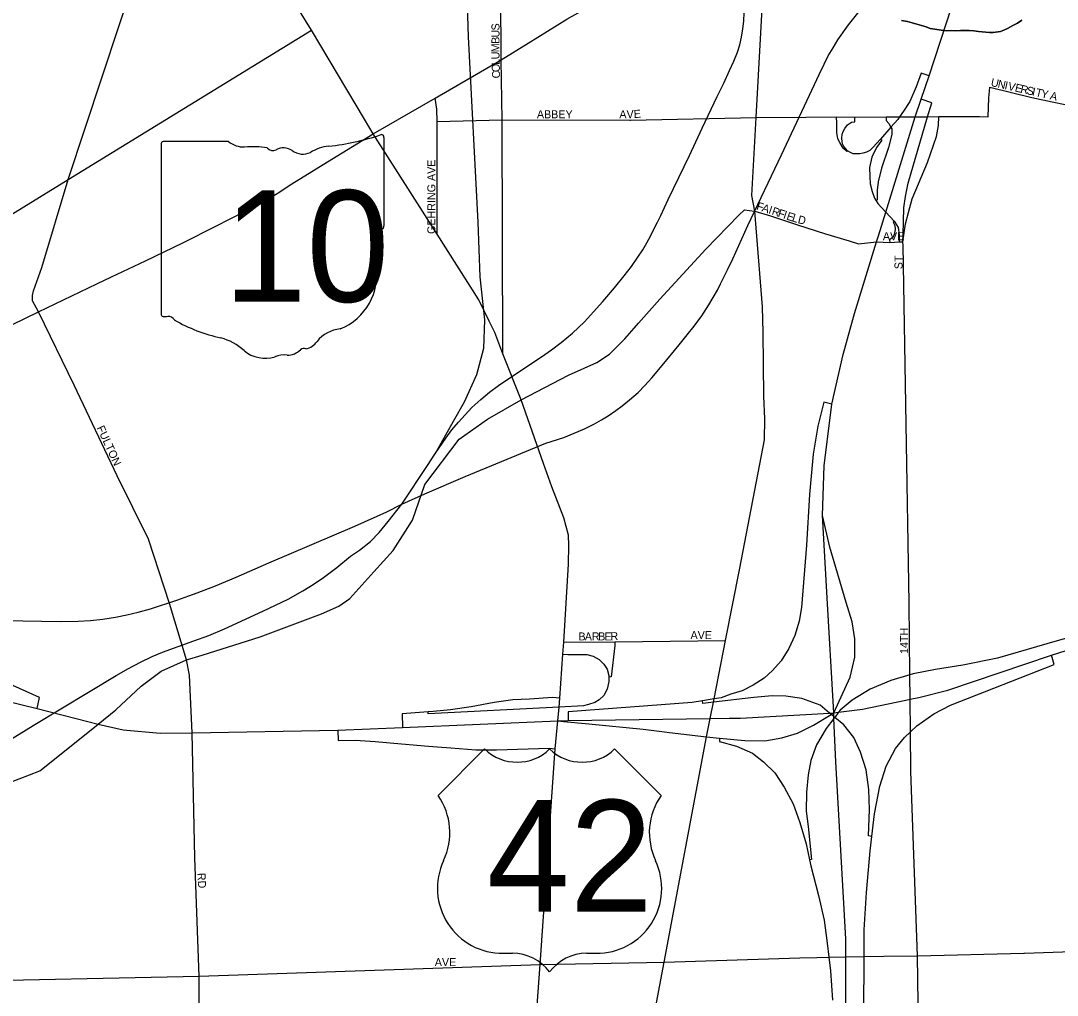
# Model space of a CAD drawing. Extents: x -561 to 1170, y 0 to 846.
# Drawn here: x 229.07 to 246.55, y 259.37 to 275.8 of the extents above; entities that cross this region are included whole.
import ezdxf

# ---------------------------------------------------------------- set-up
doc = ezdxf.new("R2010")
doc.units = 0
for name, color, linetype in [('GM_X_City_Street', 7, 'Continuous'), ('GM_X_City_Street_Text', 7, 'Continuous'), ('GM_X_Interchange_Ramps', 7, 'Continuous'), ('GM_X_Interstate_Route', 7, 'Continuous'), ('GM_X_Major_River', 7, 'Continuous'), ('GM_X_Rail_Line', 7, 'Continuous'), ('GM_X_State_Location', 7, 'Continuous'), ('GM_X_State_Route', 7, 'Continuous'), ('GM_X_State_Shield', 7, 'Continuous'), ('GM_X_US_Location', 7, 'Continuous'), ('GM_X_US_Route', 7, 'Continuous'), ('GM_X_US_Shield', 7, 'Continuous')]:
    doc.layers.add(name, color=color, linetype=linetype)

msp = doc.modelspace()

# ---------------------------------------------------------------- linework, layer by layer
at = {"layer": 'GM_X_City_Street'}
for points in [[(241.587, 270.54), (241.581, 270.976), (241.449, 272.588), (241.4, 272.851), (241.47, 274.167), (241.587, 276.31), (241.601, 276.652), (241.62, 276.918), (241.615, 277.331), (241.596, 277.763), (241.582, 278.503), (241.5, 280.566), (241.5, 280.686), (241.519, 280.834), (241.598, 281.16), (242.005, 282.324), (242.335, 283.286)], [(232.08, 259.688), (232.008, 261.687), (231.963, 263.79), (231.915, 264.765), (231.869, 265.021), (231.578, 265.97), (231.224, 267.059), (230.696, 268.124), (229.972, 269.654), (229.373, 270.892), (229.271, 271.075), (229.271, 271.165), (229.29, 271.245), (229.43, 271.639), (229.871, 273.119), (230.734, 275.717), (231.217, 277.172)], [(237.17, 275.418), (237.161, 276.52)], [(215.146, 270.207), (225.325, 270.329), (226.891, 271.29), (229.871, 273.119), (233.973, 275.638)], [(237.203, 270.179), (237.187, 274.125), (237.172, 275.138), (237.17, 275.418)], [(245.239, 274.18), (245.381, 274.179), (245.392, 274.495), (245.404, 274.608)], [(245.404, 274.608), (245.412, 274.674), (246.122, 274.503), (246.463, 274.43)], [(236.093, 272.196), (236.095, 274.098), (236.085, 274.307), (236.059, 274.49)], [(246.463, 274.43), (246.68, 274.383), (246.805, 274.341), (246.874, 274.31)], [(236.095, 274.098), (237.187, 274.125), (239.344, 274.123)], [(239.344, 274.123), (239.352, 274.123), (241.47, 274.167), (242.311, 274.171)], [(242.311, 274.171), (242.828, 274.175), (243.135, 274.172), (243.664, 274.174), (243.89, 274.174), (243.95, 274.175)], [(243.95, 274.175), (244.153, 274.175), (244.363, 274.178), (244.553, 274.18), (245.239, 274.18)], [(244.042, 272.564), (244.104, 272.793), (244.359, 273.404), (244.511, 273.846), (244.546, 274.032), (244.553, 274.18)], [(239.49, 270.7), (239.846, 271.104), (240.621, 271.945), (241.177, 272.521), (241.277, 272.607), (241.445, 272.588)], [(241.445, 272.588), (241.449, 272.588), (241.711, 272.508), (242.168, 272.356), (242.641, 272.207), (243.037, 272.087)], [(243.948, 272.006), (243.947, 272.072), (243.989, 272.373), (244.042, 272.564)], [(243.037, 272.087), (243.197, 272.038), (243.503, 272.067), (243.724, 272.06), (243.884, 272.068), (243.947, 272.072)], [(244.24, 256.524), (244.219, 257.049), (244.218, 258.034), (244.189, 260.034), (244.079, 263.14), (244.072, 263.81), (244.066, 264.357), (244.062, 264.771), (244.049, 265.982), (243.948, 272.006)], [(232.134, 265.104), (233.109, 265.408), (234.145, 265.798), (234.434, 265.928), (234.621, 266.059), (235.024, 266.504), (235.353, 266.866), (235.68, 267.38), (235.886, 267.979), (236.466, 268.745), (236.94, 269.081), (237.509, 269.405), (238.307, 269.819), (238.786, 270.035), (238.996, 270.176), (239.257, 270.435), (239.413, 270.613), (239.49, 270.7)], [(239.918, 259.925), (239.918, 259.925), (240.637, 263.724), (240.697, 264.032), (240.751, 264.307), (240.763, 264.364), (240.956, 265.347), (241.195, 266.57), (241.612, 268.73), (241.62, 269.087), (241.601, 269.468), (241.587, 270.54)], [(238.229, 265.319), (239.09, 265.328), (240.956, 265.347)], [(227.907, 262.547), (228.517, 262.813), (229.393, 263.151), (229.894, 263.549), (230.38, 263.941), (230.673, 264.178), (231.102, 264.578), (231.442, 264.83), (231.869, 265.021), (232.134, 265.104)], [(245.996, 260.076), (251.137, 260.26)], [(244.189, 260.034), (245.987, 260.076), (245.996, 260.076)], [(225.431, 259.49), (227.763, 259.6), (232.08, 259.688), (237.829, 259.885)], [(237.829, 259.885), (239.918, 259.925), (242.209, 260.001), (242.493, 260.005)], [(238.774, 253.841), (239.918, 259.925)], [(242.493, 260.005), (242.698, 260.009), (242.986, 260.014), (243.294, 260.019), (243.624, 260.025)], [(243.624, 260.025), (244.189, 260.034)], [(228.122, 248.14), (228.208, 248.321), (228.22, 248.347), (228.787, 249.591), (229.314, 250.773), (230.194, 252.768), (230.9, 254.246), (231.72, 255.969), (231.913, 256.389), (232.133, 256.831), (232.088, 258.264), (232.08, 259.688)]]:
    msp.add_lwpolyline(points, dxfattribs=at)
at = {"layer": 'GM_X_Interchange_Ramps'}
for points in [[(244.387, 274.865), (244.256, 274.911), (244.168, 274.681), (244.06, 274.436), (243.956, 274.274), (243.89, 274.174), (243.861, 274.132), (243.744, 274), (243.567, 273.8), (243.441, 273.658), (243.388, 273.611), (243.332, 273.579), (243.269, 273.563), (243.217, 273.555), (243.161, 273.552), (243.109, 273.555), (243.06, 273.574), (243.014, 273.606), (242.95, 273.677), (242.934, 273.709), (242.921, 273.756), (242.917, 273.819), (242.922, 273.884), (242.937, 273.932), (242.965, 273.981), (243.01, 274.04), (243.045, 274.067), (243.08, 274.084), (243.136, 274.09), (243.135, 274.172)], [(243.947, 272.072), (243.948, 272.19), (243.96, 272.642), (243.989, 272.831), (244.037, 273.059), (244.363, 274.178), (244.431, 274.41), (244.255, 274.474)], [(243.014, 273.606), (243.003, 273.593), (242.939, 273.651), (242.88, 273.742), (242.848, 273.808), (242.83, 273.913), (242.83, 274.068), (242.828, 274.175)], [(243.664, 274.174), (243.664, 274.116), (243.71, 274.062), (243.744, 274), (243.759, 273.973), (243.761, 273.879), (243.7, 273.662), (243.584, 273.312), (243.529, 273.079), (243.512, 272.942), (243.514, 272.779), (243.492, 272.761)], [(243.567, 273.8), (243.589, 273.783), (243.501, 273.661), (243.423, 273.496), (243.384, 273.323), (243.388, 273.17), (243.396, 273.047), (243.43, 272.917), (243.465, 272.804), (243.492, 272.761), (243.521, 272.714), (243.657, 272.567), (243.797, 272.415), (243.812, 272.399), (243.863, 272.309), (243.884, 272.19), (243.884, 272.068)], [(243.797, 272.415), (243.784, 272.402), (243.811, 272.346), (243.817, 272.285), (243.806, 272.212), (243.781, 272.15), (243.722, 272.101), (243.724, 272.06)], [(242.749, 269.335), (242.614, 269.368), (242.509, 268.961), (242.435, 268.491), (242.368, 267.811), (242.319, 266.958), (242.236, 265.903), (242.195, 265.676), (242.122, 265.431), (242.02, 265.212), (241.894, 265.007), (241.748, 264.841), (241.604, 264.712), (241.419, 264.596), (241.237, 264.5), (241.045, 264.443), (240.88, 264.384), (240.763, 264.364), (240.567, 264.331), (240.393, 264.301), (238.302, 264.146), (238.303, 263.998)], [(247.858, 265.546), (247.817, 265.695), (246.548, 265.342), (245.539, 265.05), (244.955, 264.935), (244.496, 264.862), (244.117, 264.788), (244.062, 264.771), (243.742, 264.674), (243.393, 264.531), (243.089, 264.343), (242.888, 264.173), (242.862, 264.139), (242.796, 264.053), (242.783, 264.036), (242.65, 263.863), (242.49, 263.592), (242.393, 263.326), (242.351, 263.082), (242.32, 262.79), (242.317, 262.469), (242.348, 262.215), (242.405, 261.658), (242.371, 261.651)], [(239.09, 265.328), (239.09, 265.263), (239.026, 264.735), (238.987, 264.733)], [(229.347, 264.203), (229.387, 264.387), (228.938, 264.589), (228.668, 264.75), (228.428, 264.91), (228.236, 265.03), (228.085, 265.118), (227.933, 265.166), (227.747, 265.213), (227.668, 265.222)], [(238.214, 265.116), (238.294, 265.111), (238.49, 265.111), (238.618, 265.111), (238.722, 265.087), (238.826, 265.031), (238.906, 264.951), (238.962, 264.863), (238.986, 264.759), (238.987, 264.733), (238.99, 264.655), (238.958, 264.531), (238.906, 264.423), (238.826, 264.351), (238.754, 264.303), (238.642, 264.271), (238.558, 264.247), (238.148, 264.226), (235.943, 264.111), (235.94, 264.147)], [(243.288, 259.225), (243.295, 259.868), (243.294, 260.019), (243.29, 260.469), (243.33, 261.099), (243.396, 261.803), (243.424, 262.046), (243.469, 262.427), (243.556, 262.892), (243.662, 263.231), (243.82, 263.526), (243.972, 263.716), (244.072, 263.81), (244.179, 263.911), (244.466, 264.113), (244.75, 264.259), (246.495, 264.944), (246.453, 265.099)], [(243.424, 262.046), (243.365, 262.053), (243.383, 262.501), (243.369, 262.839), (243.324, 263.166), (243.231, 263.464), (243.118, 263.711), (242.95, 263.927), (242.796, 264.053), (242.781, 264.065), (242.735, 264.102), (242.708, 264.125), (242.548, 264.256), (242.24, 264.369), (241.971, 264.411), (241.739, 264.415), (241.435, 264.388), (240.751, 264.307), (240.575, 264.287), (240.567, 264.331)], [(238.159, 264.378), (238.038, 264.385), (237.648, 264.362), (237.371, 264.351), (237.054, 264.306), (236.664, 264.232), (236.319, 264.181), (236.025, 264.153), (235.94, 264.147), (235.505, 264.113), (235.509, 263.883)], [(234.419, 263.837), (234.425, 263.661), (234.713, 263.667), (235.047, 263.644), (235.494, 263.604), (235.946, 263.565), (236.325, 263.537), (236.743, 263.508), (237.094, 263.503), (237.981, 263.531), (238.08, 263.525)], [(240.856, 263.704), (240.851, 263.648), (241.141, 263.566), (241.408, 263.449), (241.596, 263.304), (241.788, 263.119), (241.944, 262.877), (242.097, 262.594), (242.206, 262.28), (242.312, 261.919), (242.371, 261.651), (242.393, 261.549), (242.525, 261.049), (242.616, 260.633), (242.67, 260.247), (242.698, 260.009), (242.725, 259.78), (242.756, 259.285)]]:
    msp.add_lwpolyline(points, dxfattribs=at)
at = {"layer": 'GM_X_Interstate_Route'}
for points in [[(243.658, 272.569), (244.153, 274.175), (244.255, 274.474), (244.387, 274.865), (245.71, 278.914), (245.891, 279.295)], [(243.534, 272.168), (243.657, 272.567), (243.658, 272.569)], [(242.592, 267.458), (242.617, 268.294), (242.749, 269.335), (242.936, 270.169), (243.131, 270.861), (243.503, 272.067), (243.534, 272.168)], [(242.767, 264.325), (242.672, 265.969), (242.592, 267.458)], [(242.741, 264.106), (242.779, 264.129), (243.058, 264.729), (243.133, 265.067), (243.133, 265.379), (243.088, 265.662), (242.989, 265.989), (242.715, 266.922), (242.592, 267.458)], [(243.997, 264.342), (244.066, 264.357), (244.214, 264.387), (244.703, 264.513), (246.453, 265.099), (247.455, 265.423), (247.858, 265.546), (248.754, 265.763), (250.392, 266.077), (251.947, 266.344), (252.285, 266.441)], [(227.693, 264.598), (228.255, 264.473), (228.82, 264.333), (229.347, 264.203), (230.201, 263.984), (230.38, 263.941), (230.799, 263.841), (231.424, 263.788), (231.963, 263.79), (234.419, 263.837), (235.509, 263.883), (238.13, 263.995), (238.221, 263.986)], [(241.018, 264.037), (241.206, 264.039), (242.708, 264.125), (242.779, 264.129), (242.862, 264.139), (243.267, 264.192), (243.997, 264.342)], [(242.956, 257.907), (242.986, 259.222), (242.986, 260.014), (242.986, 260.317), (242.815, 263.304), (242.783, 264.036), (242.781, 264.065), (242.779, 264.129), (242.767, 264.325)], [(239.927, 263.81), (240.008, 263.8), (240.637, 263.724), (240.856, 263.704), (241.283, 263.665), (241.617, 263.66), (241.903, 263.706), (242.171, 263.786), (242.439, 263.922), (242.735, 264.102), (242.741, 264.106)], [(238.13, 263.995), (238.303, 263.998), (240.697, 264.032), (241.018, 264.037)], [(238.221, 263.986), (238.648, 263.943)], [(238.648, 263.943), (239.566, 263.852), (239.927, 263.81)]]:
    msp.add_lwpolyline(points, dxfattribs=at)
at = {"layer": 'GM_X_Major_River'}
for points in [[(243.923, 275.802), (244.021, 275.781), (244.102, 275.761), (244.178, 275.74), (244.26, 275.714), (244.336, 275.693), (244.407, 275.667), (244.483, 275.652), (244.591, 275.637), (244.678, 275.627), (244.759, 275.633), (244.84, 275.629), (244.916, 275.63), (244.992, 275.631), (245.062, 275.631), (245.143, 275.627), (245.219, 275.617), (245.284, 275.612), (245.344, 275.602), (245.404, 275.598), (245.469, 275.598), (245.506, 275.604), (245.55, 275.61), (245.593, 275.616), (245.647, 275.638), (245.711, 275.666), (245.797, 275.716), (245.878, 275.755), (245.953, 275.805)], [(245.953, 275.805), (245.878, 275.755), (245.797, 275.716), (245.711, 275.666), (245.647, 275.638), (245.593, 275.616), (245.55, 275.61), (245.506, 275.604), (245.469, 275.598), (245.404, 275.598), (245.344, 275.602), (245.284, 275.612), (245.219, 275.617), (245.143, 275.627), (245.062, 275.631), (244.992, 275.631), (244.916, 275.63), (244.84, 275.629), (244.759, 275.633), (244.678, 275.627), (244.591, 275.637), (244.483, 275.652), (244.407, 275.667), (244.336, 275.693), (244.26, 275.714), (244.178, 275.74), (244.102, 275.761), (244.021, 275.781), (243.923, 275.802)]]:
    msp.add_lwpolyline(points, dxfattribs=at)
at = {"layer": 'GM_X_Rail_Line'}
for points in [[(236.561, 277.298), (236.615, 275.526), (236.781, 272.399), (236.814, 271.478), (236.894, 270.755), (236.874, 270.272), (236.755, 269.828), (236.549, 269.364), (236.363, 269.04), (236.055, 268.489)], [(235.5, 267.647), (235.883, 267.824), (236.563, 268.114), (237.177, 268.365), (237.926, 268.677), (238.228, 268.773), (238.579, 268.919), (238.744, 268.999), (238.865, 269.068), (238.977, 269.137), (239.106, 269.225), (239.211, 269.302), (239.338, 269.406), (239.48, 269.532), (239.596, 269.647), (239.715, 269.774), (239.888, 269.985), (240.172, 270.335), (240.31, 270.504), (240.426, 270.649), (240.555, 270.824), (240.675, 271.01), (240.817, 271.253), (240.871, 271.363), (240.919, 271.461), (240.989, 271.598), (241.076, 271.784), (241.329, 272.342), (241.896, 273.535), (242.454, 274.723), (242.535, 274.893), (242.617, 275.063), (242.688, 275.203), (242.771, 275.34), (242.85, 275.472), (243.03, 275.725), (243.21, 275.951)], [(236.055, 268.489), (236.238, 268.761), (236.343, 268.898), (236.452, 269.032), (236.563, 269.155), (236.68, 269.276), (236.827, 269.41), (236.974, 269.533), (237.127, 269.65), (237.502, 269.903), (237.855, 270.132), (238.022, 270.251), (238.185, 270.373), (238.375, 270.528), (238.579, 270.723), (238.73, 270.888), (238.885, 271.063), (239.081, 271.294), (239.244, 271.495), (239.37, 271.655), (239.474, 271.809), (239.56, 271.936), (239.626, 272.051), (239.693, 272.174), (239.754, 272.292), (239.81, 272.401), (239.863, 272.515), (239.989, 272.784), (240.347, 273.523), (240.563, 273.984), (240.814, 274.517), (240.926, 274.744), (241.023, 274.956), (241.094, 275.114), (241.155, 275.264), (241.197, 275.388), (241.226, 275.517), (241.246, 275.659), (241.263, 275.787), (241.272, 275.934)], [(235.5, 267.647), (235.933, 268.301), (236.055, 268.489)], [(228.793, 265.688), (229.737, 265.67), (230.043, 265.673), (230.248, 265.685), (230.456, 265.706), (230.67, 265.74), (230.862, 265.78), (231.052, 265.826), (231.262, 265.884), (231.704, 266.027), (232.048, 266.15), (232.357, 266.269), (232.704, 266.414), (233.253, 266.656), (234.705, 267.278), (235.242, 267.517), (235.5, 267.647)], [(228.852, 263.654), (229.28, 263.916), (230.682, 264.757), (230.888, 264.876), (231.093, 264.985), (231.287, 265.077), (231.463, 265.152), (231.989, 265.343), (232.242, 265.435), (232.508, 265.547), (233.152, 265.844), (233.582, 266.048), (233.827, 266.185), (234.001, 266.291), (234.179, 266.41), (234.403, 266.578), (234.632, 266.768), (234.782, 266.869), (234.969, 267.02), (235.117, 267.172), (235.268, 267.353), (235.5, 267.647)]]:
    msp.add_lwpolyline(points, dxfattribs=at)
at = {"layer": 'GM_X_State_Route'}
for points in [[(237.628, 275.42), (238.278, 275.822), (238.929, 276.192), (239.133, 276.325), (239.408, 276.568), (239.547, 276.691)], [(235.012, 273.892), (236.059, 274.49), (237.172, 275.138), (237.628, 275.42)], [(219.308, 266.123), (220.622, 266.696), (222.711, 267.664), (225.36, 268.941), (227.581, 270.023), (228.102, 270.274), (228.711, 270.57), (229.373, 270.892), (230.356, 271.362), (230.602, 271.478), (231.174, 271.751), (231.804, 272.052), (232.359, 272.331), (232.843, 272.579), (233.092, 272.697), (233.394, 272.883), (233.645, 273.045), (234.315, 273.462), (235.012, 273.892)]]:
    msp.add_lwpolyline(points, dxfattribs=at)
at = {"layer": 'GM_X_State_Shield'}
for p, q in [((231.438, 273.71), (231.438, 270.857)), ((232.576, 273.759), (231.475, 273.759)), ((235.197, 272.337), (235.197, 273.83)), ((235.197, 272.338), (235.197, 272.337))]:
    msp.add_line(p, q, dxfattribs=at)
for centre, radius, start, end in [((233.858, 277.648), 3.986, 275.8445, 288.9065), ((235.155, 273.836), 0.0418, 351.8621, 97.738), ((231.481, 273.716), 0.0435, 98.1301, 188.1301), ((232.838, 274.09), 0.422, 231.6195, 271.1119), ((232.978, 272.157), 1.516, 80.4867, 94.9883), ((234.367, 272.888), 0.802, 97.3462, 120.7689), ((233.323, 273.731), 0.122, 219.7921, 297.1024), ((233.501, 273.401), 0.253, 54.4667, 119.1411), ((233.828, 273.853), 0.305, 233.8562, 294.8282), ((235.187, 272.228), 0.0648, 107.944, 210.337), ((235.152, 272.331), 0.0448, 289.6038, 7.7341), ((234.775, 272.039), 0.389, 340.033, 23.6496), ((235.347, 271.713), 0.283, 136.8065, 186.9296), ((234.081, 271.523), 0.997, 292.3089, 8.9858), ((231.482, 270.851), 0.0439, 171.9584, 258.3066), ((231.488, 271.143), 0.335, 267.339, 280.6039), ((231.557, 270.692), 0.121, 29.7484, 93.2717), ((233.083, 273.256), 2.879, 240.4129, 257.1985), ((234.502, 270.056), 0.546, 94.4031, 142.5768), ((232.225, 269.575), 0.901, 47.1842, 75.836), ((233.81, 270.58), 0.322, 282.8732, 323.2771), ((233.199, 270.678), 0.572, 230.7004, 286.2918), ((233.571, 270.465), 0.305, 268.777, 315.5493), ((233.847, 270.188), 0.0857, 65.7517, 132.6484), ((233.529, 269.692), 0.47, 85.6951, 111.2099)]:
    msp.add_arc(centre, radius, start, end, dxfattribs=at)
at = {"layer": 'GM_X_US_Route'}
for points in [[(234.867, 274.136), (233.973, 275.638), (232.876, 277.408), (232.812, 277.695), (232.662, 278.388), (232.623, 278.552)], [(236.971, 270.734), (236.795, 271.091), (236.093, 272.196), (235.012, 273.892), (234.867, 274.136)], [(237.888, 268.33), (237.509, 269.405), (237.203, 270.179), (237.066, 270.54), (236.971, 270.734)], [(237.37, 252.533), (237.409, 253.076), (237.543, 256.021), (237.603, 256.855), (237.663, 257.7), (237.753, 258.815), (237.829, 259.885), (238.08, 263.525), (238.13, 263.995), (238.148, 264.226), (238.159, 264.378), (238.214, 265.116), (238.229, 265.319), (238.305, 266.636), (238.313, 266.951), (238.305, 267.127), (238.23, 267.418), (238.025, 267.941), (237.888, 268.33)]]:
    msp.add_lwpolyline(points, dxfattribs=at)
at = {"layer": 'GM_X_US_Shield'}
for p, q in [((236.893, 263.521), (236.109, 262.738)), ((239.868, 262.738), (239.085, 263.521)), ((237.206, 260.075), (237.362, 260.075)), ((238.615, 260.075), (238.772, 260.075))]:
    msp.add_line(p, q, dxfattribs=at)
for centre, radius, start, end in [((237.441, 264.08), 0.783, 225.573, 314.427), ((238.537, 264.08), 0.783, 225.573, 314.427), ((235.211, 262.109), 1.096, 334.5471, 35.0009), ((240.766, 262.109), 1.096, 144.9991, 205.4529), ((237.194, 261.171), 1.096, 154.8319, 270.6383), ((238.784, 261.171), 1.096, 269.3617, 25.1681), ((237.362, 259.292), 0.783, 36.8699, 90), ((238.615, 259.292), 0.783, 90, 143.1301)]:
    msp.add_arc(centre, radius, start, end, dxfattribs=at)

# ---------------------------------------------------------------- texts
at = {"layer": 'GM_X_City_Street_Text'}
for s, rotation, p in [('S', 90, (237.144, 275.633)), ('U', 90, (237.144, 275.514)), ('B', 90, (237.144, 275.407)), ('M', 90, (237.144, 275.265)), ('U', 90.3061, (237.144, 275.146)), ('L', 91.6397, (237.147, 275.052)), ('O', 92.164, (237.152, 274.933)), ('C', 92.1858, (237.156, 274.827)), ('U', 347.3313, (245.419, 274.698)), ('N', 347.3052, (245.535, 274.672)), ('I', 347.3122, (245.651, 274.646)), ('V', 347.3052, (245.709, 274.633)), ('E', 347.3239, (245.825, 274.607)), ('R', 347.3184, (245.918, 274.586)), ('S', 347.3239, (246.022, 274.562)), ('I', 347.31, (246.115, 274.542)), ('T', 347.3239, (246.173, 274.528)), ('Y', 347.3174, (246.266, 274.508)), ('A', 347.3306, (246.416, 274.474)), ('ABBEY', 0, (237.775, 274.152)), ('A', 0.0874, (239.165, 274.152)), ('V', 1.897, (239.289, 274.152)), ('E', 3.53, (239.411, 274.156)), ('GEHRING AVE', 90, (236.063, 272.202)), ('F', 341.5996, (241.466, 272.618)), ('A', 341.5858, (241.556, 272.588)), ('I', 341.5702, (241.669, 272.551)), ('R', 341.5978, (241.725, 272.532)), ('F', 341.5737, (241.827, 272.498)), ('I', 341.6343, (241.917, 272.468)), ('E', 341.5737, (241.973, 272.449)), ('L', 342.1204, (242.065, 272.419)), ('D', 346.0412, (242.165, 272.387)), ('AVE', 0, (243.608, 272.097)), ('ST', 90, (243.939, 271.608)), ('FULTON', 294.7036, (230.35, 268.934)), ('B', 0.17, (238.476, 265.349)), ('A', 0.1729, (238.583, 265.349)), ('R', 0.184, (238.702, 265.35)), ('B', 0.17, (238.809, 265.35)), ('E', 0.1639, (238.916, 265.35)), ('R', 2.8671, (239.018, 265.351)), ('AVE', 0, (240.365, 265.373)), ('14TH', 90, (244.034, 265.122)), ('RD', 273.011, (232.051, 261.428)), ('AVE', 0, (236.053, 259.86))]:
    msp.add_text(s, height=0.135, rotation=rotation, dxfattribs=at).set_placement(p)
at = {"layer": 'GM_X_State_Location'}
for s in ['s', 'r']:
    msp.add_text(s, height=0.0027, dxfattribs=at).set_placement((233.275, 272.094))
msp.add_text('10', height=0.0027, rotation=0, dxfattribs=at).set_placement((232.595, 271.897))
at = {"layer": 'GM_X_State_Shield'}
msp.add_text('10', height=1.8795, dxfattribs=at).set_placement((232.492, 271.058))
at = {"layer": 'GM_X_US_Location'}
for s in ['0', '/']:
    msp.add_text(s, height=0.0027, dxfattribs=at).set_placement((237.988, 261.705))
msp.add_text('42', height=0.0027, rotation=0, dxfattribs=at).set_placement((237.431, 261.146))
at = {"layer": 'GM_X_US_Shield'}
msp.add_text('42', height=1.8795, dxfattribs=at).set_placement((236.931, 260.78))

doc.saveas('drawing.dxf')
